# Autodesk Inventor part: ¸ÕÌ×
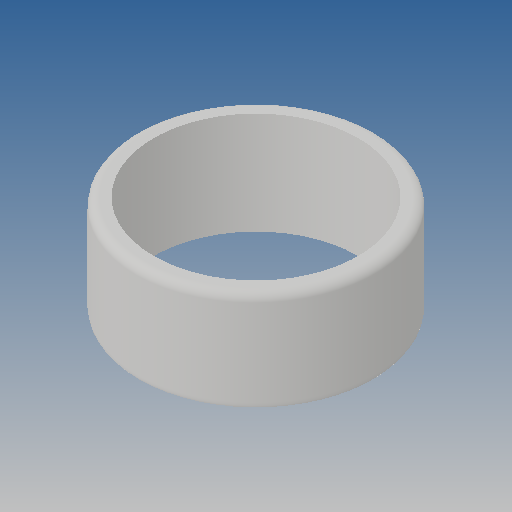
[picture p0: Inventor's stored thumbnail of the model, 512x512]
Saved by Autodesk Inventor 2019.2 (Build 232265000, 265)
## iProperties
Created: 2013-07
Part Number: ¸ÕÌ×
Material: Ogólny
Document SubType Name: Modeling
Designer: CADENGINEERING4
Density: 1 g/cm^3
Appearance: Domyślna
Author: CADENGINEERING4
Revision Number: ÈÎºÎ
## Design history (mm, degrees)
feature "Ô²½Ç2"
node "Bryła1"
